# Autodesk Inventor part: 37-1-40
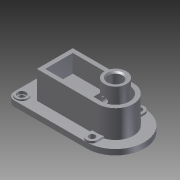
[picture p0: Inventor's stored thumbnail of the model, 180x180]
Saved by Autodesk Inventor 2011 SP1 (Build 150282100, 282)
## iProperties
Created: 2014-02
Part Number: 37-1-40
Document SubType Name: Modeling
Designer: Administrator
Density: 1 g/cm^3
Author: Administrator
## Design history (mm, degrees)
sketch "草图1"
  geometry: L1 (-105, 42)-(0, 42); L2 (0, -42)-(-105, -42); L3 (-116, -31)-(-116, 31); A1 r 11 centre (-105, 31) between (-105, 42) and (-116, 31); A2 r 11 centre (-105, -31) between (-116, -31) and (-105, -42); A3 r 42 centre (0, 0) between (0, -42) and (0, 42); 3 further points
  constraints: 6 end point, 6 point on circle, 4 tangent, 3 centre point, 2 coincident, 2 point on line, 1 equal radius, 1 horizontal, 1 parallel
  dimensions: "d0" = 84 distance of L1.end L2.start; "d1" = 116 distance of L2.start point (-116, -42); "d2" = 11 radius of A1
extrude "拉伸1" new body sketch "草图1" distance "d3" = 8; taper "d4" = 0 deg
sketch "草图2"
  geometry: L1 (-88, 26)-(0, 26); L2 (0, -26)-(-88, -26); L3 (-88, -26)-(-88, 26); A1 r 42 centre (0, 0) between (0, -42) and (0, 42) reference; A2 r 26 centre (0, 0) between (0, -26) and (0, 26); 1 further point
  constraints: 6 end point, 2 coincident, 2 point on circle, 1 centre point, 1 horizontal, 1 parallel
  dimensions: "d5" = 88 distance of L1.start L1.end; "d6" = 52 distance of L2.end L1.start
extrude "拉伸2" join sketch "草图2" distance "d7" = 40; taper "d8" = 0 deg
sketch "草图3"
  geometry: L1 (-82, 20)-(0, 20); L2 (0, -20)-(-82, -20); L3 (-82, -20)-(-82, 20); A1 r 26 centre (0, 0) between (0, -26) and (0, 26) reference; A2 r 20 centre (0, 0) between (0, -20) and (0, 20); 1 further point
  constraints: 6 end point, 2 coincident, 2 point on circle, 1 centre point, 1 horizontal, 1 parallel
  dimensions: "d9" = 40 distance of L2.end L1.start; "d10" = 82 distance of L2.start L2.end
extrude "拉伸3" cut sketch "草图3" distance "d11" = 26; taper "d12" = 0 deg
sketch "草图4"
  geometry: L1 (0, 20)-(-82, 20) reference; L2 (-69, 5)-(-53, 5); L3 (-69, -5)-(-53, -5); A1 r 20 centre (0, 0) between (0, -20) and (0, 20) reference; A2 r 5 centre (-69, 0) between (-69, 5) and (-69, -5); A3 r 5 centre (-53, 0) between (-53, -5) and (-53, 5)
  constraints: 4 end point, 4 point on circle, 2 centre point, 2 tangent, 1 parallel
  dimensions: "d13" = 10 diameter of A2; "d14" = 16 distance of L2.start L2.end; "d15" = 53 distance of A1.centre A3.centre
extrude "拉伸4" cut sketch "草图4" stored distance "d16" = 26; taper "d17" = 0 deg
sketch "草图5"
  geometry: C1 r 16 at (0, 0); A1 r 20 centre (0, 0) between (0, -20) and (0, 20) reference
  constraints: 1 centre point, 1 coincident
  dimensions: "d18" = 32 diameter of C1
extrude "拉伸5" join sketch "草图5" distance "d19" = 46; taper "d20" = 0 deg
hole "Hole1" diameter "d23" = 20; stored, may be unused: countersink angle "d27" = 90 deg, drill point angle "d29" = 118 deg; dims "d21" = 10, "d22" = 10, "d24" = 6, "d25" = 4, "d26" = 2, "d28" = 8
chamfer "倒角1" distance "d30" = 2; stored, may be unused: second distance "d31" = 2, angle "d32" = 45 deg
sketch "草图6"
  geometry: C1 r 9 at (-105, 31); A1 r 11 centre (-105, 31) between (-105, 42) and (-116, 31) reference
  constraints: 1 centre point, 1 coincident
  dimensions: "d33" = 18 diameter of C1
extrude "拉伸6" join sketch "草图6" distance "d34" = 2; taper "d35" = 0 deg
hole "Hole2" diameter "d38" = 9; stored, may be unused: countersink angle "d42" = 90 deg, drill point angle "d44" = 0 deg; dims "d36" = 10, "d37" = 10, "d39" = 6, "d40" = 12, "d41" = 4, "d43" = 8
mirror "镜像1"
sketch "草图7"
  geometry: L1 (0, 22)-(82, 22) reference; L2 (16, 22)-(16, 68) reference; L3 (16, 44)-(38, 22); 1 further point
  constraints: 2 end point, 2 point on line
  dimensions: "d45" = 38 distance of L3.end L1.start; "d46" = 22 distance of L2.start L3.start
feature "加强筋1" sketch "草图7" dims "d47" = 1, "d48" = 5, "d49" = 0
sketch "草图8"
  geometry: L1 (-16, 22)-(-16, 68) reference; L2 (-20, 48)-(-20, 22) reference; L3 (16, 44)-(16, 68) reference; L4 (-16, 44)-(-20, 44); 1 further point
  constraints: 2 end point, 2 point on line, 1 perpendicular
feature "加强筋2" sketch "草图8" dims "d50" = 1, "d51" = 5, "d52" = 0
sketch "草图9"
  geometry: L1 (82, 48)-(0, 48) reference; C1 r 4.5 at (0, 48); 1 further point
  constraints: 1 centre point, 1 coincident
  dimensions: "d53" = 9 diameter of C1
extrude "拉伸7" cut sketch "草图9" distance "d54" = 17; taper "d56" = 0 deg; dims "d55" = 17, "d57" = 0
sketch "草图10"
  geometry: L1 (-88, 26)-(0, 26) reference; L2 (-8, 34)-(-8, 26); L3 (8, 34)-(8, 24.739); A1 r 42 centre (0, 0) between (0, -42) and (0, 42) reference; A2 r 26 centre (0, 0) between (0, -26) and (0, 26) reference; A3 r 8 centre (0, 34) between (8, 34) and (-8, 34)
  constraints: 4 end point, 4 point on circle, 2 tangent, 1 centre point, 1 parallel, 1 perpendicular, 1 point on line
  dimensions: "d58" = 16 diameter of A3; "d59" = 34 distance of A1.centre A3.centre
extrude "拉伸8" join sketch "草图10" distance "d60" = 3; taper "d61" = 0 deg
hole "Hole3" diameter "d64" = 9; stored, may be unused: countersink angle "d68" = 90 deg, drill point angle "d70" = 118 deg; dims "d62" = 10, "d63" = 10, "d65" = 6, "d66" = 12, "d67" = 4, "d69" = 8
mirror "镜像2"
node "实体1"
